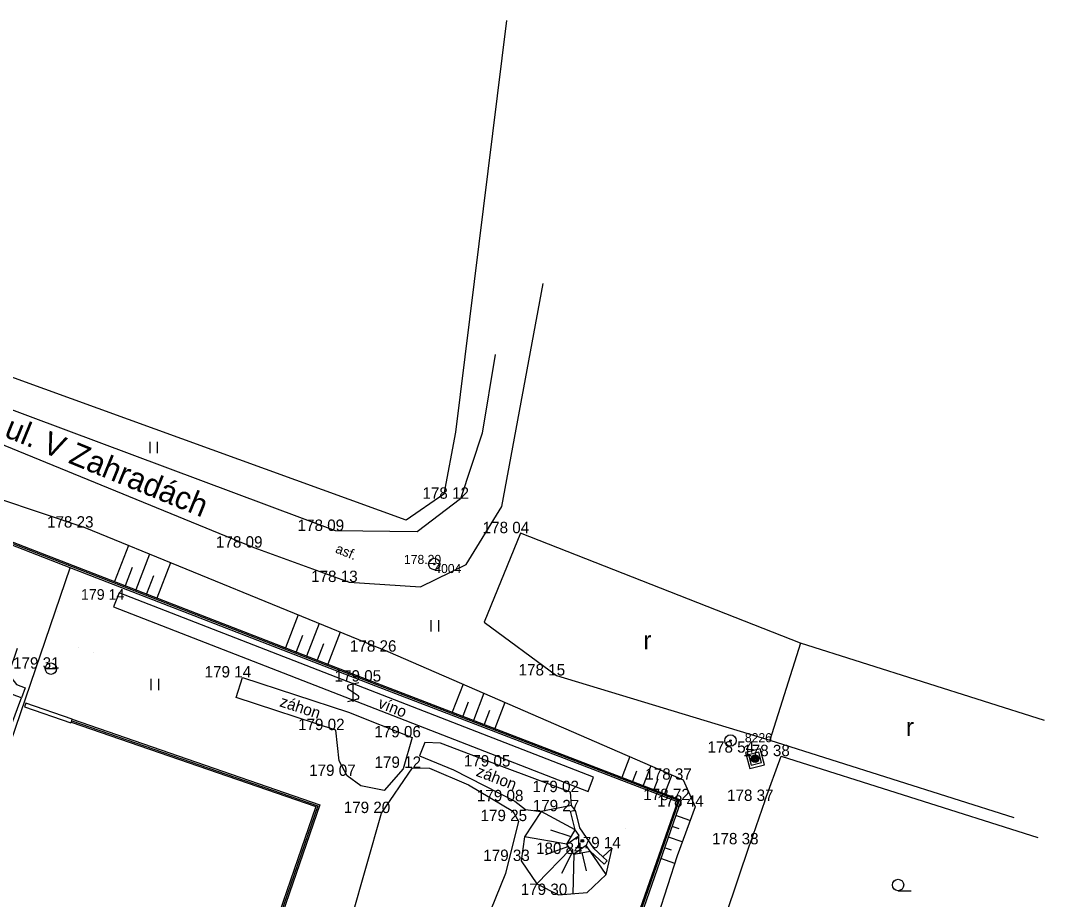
# Model space of a CAD drawing. Extents: x -537755 to -537431, y -1180722 to -1180510.
# Drawn here: x -537505 to -537437.5, y -1180574 to -1180516.1 of the extents above; entities that cross this region are included whole.
import ezdxf

# ---------------------------------------------------------------- set-up
doc = ezdxf.new("R2010")
doc.units = 0
for name, color, linetype in [('Vrstva 1', 7, 'Continuous'), ('Vrstva 10', 7, 'Continuous'), ('Vrstva 11', 7, 'Continuous'), ('Vrstva 14', 7, 'Continuous'), ('Vrstva 15', 7, 'Continuous'), ('Vrstva 21', 7, 'Continuous'), ('Vrstva 22', 7, 'Continuous'), ('Vrstva 23', 7, 'Continuous'), ('Vrstva 25', 7, 'Continuous'), ('Vrstva 3', 7, 'Continuous'), ('Vrstva 35', 7, 'Continuous'), ('Vrstva 36', 7, 'Continuous'), ('Vrstva 39', 7, 'Continuous'), ('Vrstva 40', 7, 'Continuous'), ('Vrstva 41', 7, 'Continuous'), ('Vrstva 49', 7, 'Continuous'), ('Vrstva 5', 7, 'Continuous'), ('Vrstva 7', 7, 'Continuous'), ('Vrstva 8', 7, 'Continuous')]:
    doc.layers.add(name, color=color, linetype=linetype)

msp = doc.modelspace()

# ---------------------------------------------------------------- linework, layer by layer
at = {"layer": 'Vrstva 1'}
for p, q in [((-537474.54, -1180543.31), (-537474.54, -1180543.31)), ((-537475.97, -1180547.63), (-537475.97, -1180547.63)), ((-537473.23, -1180548.13), (-537473.23, -1180548.13)), ((-537500.72, -1180549.53), (-537500.72, -1180549.53)), ((-537484.2, -1180549.75), (-537484.2, -1180549.75)), ((-537478.81, -1180549.8), (-537478.81, -1180549.8)), ((-537472, -1180549.9), (-537472, -1180549.9)), ((-537489.58, -1180550.85), (-537489.58, -1180550.85)), ((-537475.59, -1180551.97), (-537475.59, -1180551.97)), ((-537500.94, -1180552.35), (-537500.94, -1180552.35)), ((-537483.31, -1180553.12), (-537483.31, -1180553.12)), ((-537478.6, -1180553.43), (-537478.6, -1180553.43)), ((-537498.65, -1180554.29), (-537498.65, -1180554.29)), ((-537502.53, -1180555.07), (-537502.53, -1180555.07)), ((-537474.39, -1180555.77), (-537474.39, -1180555.77)), ((-537501.16, -1180557.42), (-537501.16, -1180557.42)), ((-537500.15, -1180557.78), (-537500.15, -1180557.78)), ((-537480.75, -1180557.71), (-537480.75, -1180557.71)), ((-537502.96, -1180558.83), (-537502.96, -1180558.83)), ((-537490.33, -1180559.41), (-537490.33, -1180559.41)), ((-537469.63, -1180559.28), (-537469.63, -1180559.28)), ((-537504.66, -1180560.09), (-537504.66, -1180560.09)), ((-537481.76, -1180559.68), (-537481.76, -1180559.68)), ((-537501.67, -1180562.13), (-537501.67, -1180562.13)), ((-537501.59, -1180562.27), (-537501.59, -1180562.27)), ((-537483.34, -1180561.7), (-537483.34, -1180561.7)), ((-537484.17, -1180562.88), (-537484.17, -1180562.88)), ((-537479.14, -1180563.36), (-537479.14, -1180563.36)), ((-537455.57, -1180563.55), (-537455.57, -1180563.55)), ((-537478.32, -1180563.69), (-537478.32, -1180563.69)), ((-537477.27, -1180563.74), (-537477.27, -1180563.74)), ((-537456.21, -1180564.11), (-537456.21, -1180564.11)), ((-537483.97, -1180564.91), (-537483.97, -1180564.91)), ((-537478.66, -1180564.57), (-537478.66, -1180564.57)), ((-537457.173, -1180564.368), (-537457.173, -1180564.368)), ((-537456.3, -1180564.34), (-537456.3, -1180564.34)), ((-537454.82, -1180564.6), (-537454.82, -1180564.6)), ((-537479.74, -1180565.44), (-537479.74, -1180565.44)), ((-537479.13, -1180565.37), (-537479.13, -1180565.37)), ((-537478, -1180565.4), (-537478, -1180565.4)), ((-537476.42, -1180565.51), (-537476.42, -1180565.51)), ((-537473.24, -1180565.28), (-537473.24, -1180565.28)), ((-537456.79, -1180565.19), (-537456.79, -1180565.19)), ((-537483.44, -1180565.9), (-537483.44, -1180565.9)), ((-537461.28, -1180566.15), (-537461.28, -1180566.15)), ((-537482.54, -1180566.55), (-537482.54, -1180566.55)), ((-537480.99, -1180566.87), (-537480.99, -1180566.87)), ((-537475.44, -1180566.5), (-537475.44, -1180566.5)), ((-537468.72, -1180566.97), (-537468.72, -1180566.97)), ((-537467.37, -1180566.46), (-537467.37, -1180566.46)), ((-537472.38, -1180567.57), (-537472.38, -1180567.57)), ((-537461.55, -1180567.55), (-537461.55, -1180567.55)), ((-537461.41, -1180567.5), (-537461.41, -1180567.5)), ((-537455.89, -1180567.55), (-537455.89, -1180567.55)), ((-537485.37, -1180567.87), (-537485.37, -1180567.87)), ((-537481.16, -1180568.35), (-537481.16, -1180568.35)), ((-537472.52, -1180568.22), (-537472.52, -1180568.22)), ((-537471.67, -1180568.12), (-537471.67, -1180568.12)), ((-537470.65, -1180568.25), (-537470.65, -1180568.25)), ((-537468.7, -1180568.23), (-537468.7, -1180568.23)), ((-537468.64, -1180567.85), (-537468.64, -1180567.85)), ((-537460.5, -1180567.93), (-537460.5, -1180567.93)), ((-537472.14, -1180568.88), (-537472.14, -1180568.88)), ((-537486, -1180569.4), (-537486, -1180569.4)), ((-537468.4, -1180569.46), (-537468.4, -1180569.46)), ((-537465.07, -1180569.38), (-537465.07, -1180569.38)), ((-537471.74, -1180569.92), (-537471.74, -1180569.92)), ((-537486.39, -1180570.69), (-537486.39, -1180570.69)), ((-537468.48, -1180571.05), (-537468.48, -1180571.05)), ((-537467.42, -1180570.86), (-537467.42, -1180570.86)), ((-537465.96, -1180570.67), (-537465.96, -1180570.67)), ((-537456.88, -1180570.41), (-537456.88, -1180570.41)), ((-537471.96, -1180571.51), (-537471.96, -1180571.51)), ((-537466.79, -1180571.44), (-537466.79, -1180571.44)), ((-537461.68, -1180571.17), (-537461.68, -1180571.17)), ((-537473, -1180572.34), (-537473, -1180572.34)), ((-537469.49, -1180573.75), (-537469.49, -1180573.75)), ((-537467.61, -1180573.58), (-537467.61, -1180573.58))]:
    msp.add_line(p, q, dxfattribs=at)
at = {"layer": 'Vrstva 10'}
for p, q in [((-537473.23, -1180548.13), (-537470.52, -1180533.43)), ((-537473.68, -1180538.12), (-537474.54, -1180543.31)), ((-537484.2, -1180549.75), (-537506.9, -1180541.26)), ((-537506.96, -1180543.74), (-537489.58, -1180550.85)), ((-537475.59, -1180551.97), (-537473.23, -1180548.13)), ((-537478.81, -1180549.8), (-537484.2, -1180549.75)), ((-537489.58, -1180550.85), (-537483.31, -1180553.12))]:
    msp.add_line(p, q, dxfattribs=at)
for points in [[(-537474.54, -1180543.31), (-537475.97, -1180547.63), (-537478.81, -1180549.8)], [(-537483.31, -1180553.12), (-537478.6, -1180553.43), (-537475.59, -1180551.97)], [(-537456.97, -1180564.52), (-537456.79, -1180565.19), (-537456.12, -1180565.01), (-537456.3, -1180564.34), (-537456.97, -1180564.52)]]:
    msp.add_lwpolyline(points, dxfattribs=at)
at = {"layer": 'Vrstva 11'}
for points in [[(-537505.19, -1180557.5), (-537505.76, -1180559.19), (-537505.24, -1180559.87), (-537504.66, -1180560.09), (-537504.902, -1180560.752)], [(-537505.93, -1180563.54), (-537505.011, -1180561.039), (-537504.902, -1180560.752), (-537505.211, -1180560.635), (-537506.757, -1180560.051)], [(-537457.173, -1180564.368), (-537456.891, -1180565.423), (-537455.927, -1180565.164), (-537456.21, -1180564.11), (-537457.173, -1180564.368)]]:
    msp.add_lwpolyline(points, dxfattribs=at)
at = {"layer": 'Vrstva 14'}
for p, q in [((-537514.76, -1180544.83), (-537500.72, -1180549.53)), ((-537500.72, -1180549.53), (-537480.75, -1180557.71)), ((-537480.75, -1180557.71), (-537461.28, -1180566.15)), ((-537468.941, -1180570.391), (-537468.4, -1180569.46)), ((-537468.48, -1180571.05), (-537467.42, -1180570.86))]:
    msp.add_line(p, q, dxfattribs=at)
for points in [[(-537461.28, -1180566.15), (-537460.5, -1180567.93), (-537461.68, -1180571.17), (-537462.95, -1180575.12)], [(-537468.409, -1180568.159), (-537468.64, -1180567.85), (-537470.65, -1180568.25), (-537471.74, -1180569.92), (-537471.96, -1180571.51), (-537470.938, -1180573.026), (-537469.49, -1180573.75)], [(-537469.49, -1180573.75), (-537467.61, -1180573.58), (-537466.353, -1180572.39), (-537465.96, -1180570.67), (-537466.569, -1180571.235)]]:
    msp.add_lwpolyline(points, dxfattribs=at)
at = {"layer": 'Vrstva 15'}
for p, q in [((-537497.846, -1180550.707), (-537498.771, -1180553.095)), ((-537496.458, -1180551.276), (-537497.372, -1180553.637)), ((-537495.069, -1180551.845), (-537495.973, -1180554.178)), ((-537497.609, -1180552.172), (-537498.071, -1180553.366)), ((-537496.21, -1180552.713), (-537496.672, -1180553.908)), ((-537486.662, -1180555.288), (-537487.502, -1180557.457)), ((-537485.274, -1180555.857), (-537486.103, -1180557.999)), ((-537486.383, -1180556.644), (-537486.803, -1180557.728)), ((-537483.886, -1180556.426), (-537484.704, -1180558.54)), ((-537484.984, -1180557.185), (-537485.404, -1180558.27)), ((-537475.796, -1180559.857), (-537476.504, -1180561.7)), ((-537474.419, -1180560.454), (-537475.104, -1180562.238)), ((-537475.45, -1180561.047), (-537475.804, -1180561.969)), ((-537474.05, -1180561.586), (-537474.404, -1180562.507)), ((-537473.041, -1180561.052), (-537473.704, -1180562.776)), ((-537464.788, -1180564.629), (-537465.315, -1180565.999)), ((-537464.352, -1180565.583), (-537464.615, -1180566.268)), ((-537463.411, -1180565.226), (-537463.915, -1180566.537)), ((-537462.951, -1180566.121), (-537463.215, -1180566.806)), ((-537462.033, -1180565.823), (-537462.515, -1180567.076)), ((-537468.4, -1180569.46), (-537470.65, -1180568.25)), ((-537460.833, -1180568.844), (-537461.765, -1180568.518)), ((-537468.671, -1180569.925), (-537470.004, -1180569.487)), ((-537461.556, -1180569.386), (-537462.012, -1180569.227)), ((-537468.941, -1180570.391), (-537471.74, -1180569.92)), ((-537461.346, -1180570.253), (-537462.259, -1180569.935)), ((-537468.711, -1180570.72), (-537470.938, -1180573.026)), ((-537468.832, -1180570.547), (-537470.362, -1180571.109)), ((-537468.575, -1180570.915), (-537469.306, -1180572.334)), ((-537468.48, -1180571.05), (-537468.55, -1180573.665)), ((-537467.648, -1180572.165), (-537467.95, -1180570.955)), ((-537466.353, -1180572.39), (-537467.42, -1180570.86)), ((-537462.05, -1180570.802), (-537462.507, -1180570.643)), ((-537461.841, -1180571.67), (-537462.754, -1180571.351))]:
    msp.add_line(p, q, dxfattribs=at)
at = {"layer": 'Vrstva 21'}
for p, q in [((-537498.469, -1180553.824), (-537498.831, -1180554.756)), ((-537467.189, -1180565.994), (-537498.469, -1180553.824)), ((-537498.831, -1180554.756), (-537467.551, -1180566.926)), ((-537467.551, -1180566.926), (-537467.189, -1180565.994))]:
    msp.add_line(p, q, dxfattribs=at)
for centre, radius in [((-537477.69, -1180551.93), 0.375), ((-537477.69, -1180551.93), 0.05), ((-537458.163, -1180563.571), 0.375), ((-537458.163, -1180563.571), 0.05)]:
    msp.add_circle(centre, radius, dxfattribs=at)
at = {"layer": 'Vrstva 23'}
for p, q in [((-537472, -1180549.9), (-537474.39, -1180555.77)), ((-537453.546, -1180557.157), (-537472, -1180549.9)), ((-537474.39, -1180555.77), (-537469.63, -1180559.28)), ((-537453.546, -1180557.157), (-537455.57, -1180563.55)), ((-537437.46, -1180562.25), (-537453.546, -1180557.157)), ((-537490.76, -1180560.721), (-537490.33, -1180559.41)), ((-537490.33, -1180559.41), (-537483.34, -1180561.7)), ((-537469.63, -1180559.28), (-537455.57, -1180563.55)), ((-537484.17, -1180562.88), (-537490.76, -1180560.721)), ((-537455.57, -1180563.55), (-537439.484, -1180568.643)), ((-537483.15, -1180575.31), (-537481.16, -1180568.35)), ((-537471.67, -1180568.12), (-537470.65, -1180568.25)), ((-537473, -1180572.34), (-537475.54, -1180578.6))]:
    msp.add_line(p, q, dxfattribs=at)
for points in [[(-537483.34, -1180561.7), (-537479.14, -1180563.36), (-537479.74, -1180565.44), (-537480.99, -1180566.87)], [(-537480.99, -1180566.87), (-537482.54, -1180566.55), (-537483.44, -1180565.9), (-537483.97, -1180564.91), (-537484.17, -1180562.88)], [(-537473.24, -1180565.28), (-537477.27, -1180563.74), (-537478.32, -1180563.69), (-537478.66, -1180564.57), (-537476.42, -1180565.51)], [(-537481.16, -1180568.35), (-537479.13, -1180565.37), (-537478, -1180565.4), (-537475.44, -1180566.5)], [(-537476.42, -1180565.51), (-537472.38, -1180567.57), (-537471.67, -1180568.12)], [(-537468.64, -1180567.85), (-537468.72, -1180566.97), (-537473.24, -1180565.28)], [(-537475.44, -1180566.5), (-537472.52, -1180568.22), (-537472.14, -1180568.88), (-537473, -1180572.34)]]:
    msp.add_lwpolyline(points, dxfattribs=at)
at = {"layer": 'Vrstva 25'}
for radius in [0.25, 0.2, 0.15, 0.1, 0.05]:
    msp.add_circle((-537456.544, -1180564.764), radius, dxfattribs=at)
at = {"layer": 'Vrstva 35'}
msp.add_line((-537503.335, -1180558.83), (-537502.585, -1180558.83), dxfattribs=at)
msp.add_circle((-537502.96, -1180558.83), 0.375, dxfattribs=at)
at = {"layer": 'Vrstva 36'}
for p, q in [((-537496.43, -1180544.626), (-537496.43, -1180543.876)), ((-537495.93, -1180544.626), (-537495.93, -1180543.876)), ((-537477.888, -1180556.38), (-537477.888, -1180555.63)), ((-537477.388, -1180556.38), (-537477.388, -1180555.63)), ((-537496.357, -1180560.252), (-537496.357, -1180559.502)), ((-537495.857, -1180560.252), (-537495.857, -1180559.502)), ((-537483.365, -1180560.171), (-537482.711, -1180560.607)), ((-537482.665, -1180559.764), (-537483.326, -1180559.923)), ((-537483.04, -1180561.014), (-537483.04, -1180559.764)), ((-537482.75, -1180560.852), (-537483.415, -1180561.014)), ((-537447.116, -1180573.467), (-537446.241, -1180573.467))]:
    msp.add_line(p, q, dxfattribs=at)
msp.add_circle((-537447.116, -1180573.092), 0.375, dxfattribs=at)
for centre, start, end in [((-537483.265, -1180560.06), 113.96482, 228.0101), ((-537482.814, -1180560.716), 295.55354, 46.6612)]:
    msp.add_arc(centre, 0.15, start, end, dxfattribs=at)
at = {"layer": 'Vrstva 39'}
for radius in [0.09, 0.0398]:
    msp.add_circle((-537467.929, -1180570.189), radius, dxfattribs=at)
at = {"layer": 'Vrstva 5'}
for p, q in [((-537468.7, -1180568.23), (-537468.409, -1180568.159)), ((-537468.4, -1180569.46), (-537468.7, -1180568.23)), ((-537468.409, -1180568.159), (-537468.122, -1180569.334)), ((-537468.141, -1180569.83), (-537468.4, -1180569.46)), ((-537468.122, -1180569.334), (-537467.193, -1180570.661)), ((-537468.941, -1180570.391), (-537468.141, -1180569.83)), ((-537468.48, -1180571.05), (-537468.941, -1180570.391)), ((-537467.679, -1180570.49), (-537468.48, -1180571.05)), ((-537467.42, -1180570.86), (-537467.679, -1180570.49)), ((-537466.489, -1180571.718), (-537467.42, -1180570.86)), ((-537467.193, -1180570.661), (-537466.569, -1180571.235)), ((-537466.569, -1180571.235), (-537466.285, -1180571.497)), ((-537466.285, -1180571.497), (-537466.489, -1180571.718))]:
    msp.add_line(p, q, dxfattribs=at)
at = {"layer": 'Vrstva 7'}
for p, q in [((-537515.555, -1180546.598), (-537481.76, -1180559.68)), ((-537481.796, -1180559.773), (-537515.381, -1180546.773)), ((-537501.7, -1180552.176), (-537515.2, -1180546.95)), ((-537505.614, -1180563.66), (-537501.7, -1180552.176)), ((-537481.832, -1180559.867), (-537501.7, -1180552.176)), ((-537461.663, -1180567.617), (-537481.832, -1180559.867)), ((-537461.55, -1180567.55), (-537481.796, -1180559.773)), ((-537481.76, -1180559.68), (-537461.41, -1180567.5)), ((-537504.7, -1180561.35), (-537501.65, -1180562.41)), ((-537501.59, -1180562.27), (-537485.37, -1180567.87)), ((-537501.565, -1180562.166), (-537485.241, -1180567.802)), ((-537501.631, -1180562.355), (-537485.495, -1180567.926)), ((-537455.89, -1180567.55), (-537454.82, -1180564.6)), ((-537454.82, -1180564.6), (-537437.89, -1180569.96)), ((-537477.608, -1180613.623), (-537461.55, -1180567.55)), ((-537461.41, -1180567.5), (-537475.176, -1180606.957)), ((-537461.663, -1180567.617), (-537473.031, -1180600.103)), ((-537485.37, -1180567.87), (-537494, -1180592.9)), ((-537485.241, -1180567.802), (-537493.873, -1180592.838)), ((-537486.442, -1180570.674), (-537494.127, -1180592.962)), ((-537458.47, -1180575.1), (-537456.88, -1180570.41))]:
    msp.add_line(p, q, dxfattribs=at)
for points in [[(-537472.921, -1180516.1), (-537476.295, -1180543.235)], [(-537479.535, -1180549.052), (-537507.134, -1180539.034)], [(-537476.295, -1180543.235), (-537477.068, -1180547.319)], [(-537477.068, -1180547.319), (-537479.535, -1180549.052)], [(-537501.65, -1180562.41), (-537501.631, -1180562.355), (-537501.59, -1180562.27), (-537501.565, -1180562.166), (-537504.615, -1180561.106), (-537504.7, -1180561.35)], [(-537485.495, -1180567.926), (-537486, -1180569.4), (-537486.442, -1180570.674)]]:
    msp.add_lwpolyline(points, dxfattribs=at)
at = {"layer": 'Vrstva 8'}
msp.add_line((-537455.89, -1180567.55), (-537456.88, -1180570.41), dxfattribs=at)

# ---------------------------------------------------------------- texts
at = {"layer": 'Vrstva 22'}
msp.add_text('178.20 ', height=0.6, dxfattribs=at).set_placement((-537479.69, -1180551.93))
at = {"layer": 'Vrstva 23'}
for s, p in [('4004', (-537477.69, -1180552.53)), ('8226', (-537457.215, -1180563.682))]:
    msp.add_text(s, height=0.6, dxfattribs=at).set_placement(p)
at = {"layer": 'Vrstva 3'}
for s, height, p in [('178 12 ', 0.75, (-537478.47, -1180547.63)), ('178 23 ', 0.75, (-537503.22, -1180549.53)), ('178 09 ', 0.75, (-537486.7, -1180549.75)), ('178 04 ', 0.75, (-537474.5, -1180549.9)), ('178 09 ', 0.75, (-537492.08, -1180550.85)), ('178 13 ', 0.75, (-537485.81, -1180553.12)), ('179 14 ', 0.7, (-537500.983, -1180554.29)), ('178 26 ', 0.75, (-537483.25, -1180557.71)), ('179 31 ', 0.75, (-537505.46, -1180558.83)), ('179 14 ', 0.75, (-537492.83, -1180559.41)), ('178 15 ', 0.75, (-537472.13, -1180559.28)), ('179 05 ', 0.75, (-537484.26, -1180559.68)), ('179 02 ', 0.75, (-537486.67, -1180562.88)), ('179 06 ', 0.75, (-537481.64, -1180563.36)), ('178 54 ', 0.75, (-537459.673, -1180564.368)), ('178 38 ', 0.75, (-537457.32, -1180564.6)), ('179 12 ', 0.75, (-537481.63, -1180565.37)), ('179 05 ', 0.75, (-537475.74, -1180565.28)), ('179 07 ', 0.75, (-537485.94, -1180565.9)), ('178 37 ', 0.75, (-537463.78, -1180566.15)), ('179 02 ', 0.75, (-537471.22, -1180566.97)), ('179 08 ', 0.75, (-537474.88, -1180567.57)), ('178 72 ', 0.75, (-537463.91, -1180567.5)), ('178 37 ', 0.75, (-537458.39, -1180567.55)), ('179 20 ', 0.75, (-537483.66, -1180568.35)), ('179 27 ', 0.75, (-537471.2, -1180568.23)), ('178 44 ', 0.75, (-537463, -1180567.93)), ('179 25 ', 0.75, (-537474.64, -1180568.88)), ('178 38 ', 0.75, (-537459.38, -1180570.41)), ('180 84 ', 0.75, (-537470.98, -1180571.05)), ('179 14 ', 0.75, (-537468.46, -1180570.67)), ('179 33 ', 0.75, (-537474.46, -1180571.51)), ('179 30 ', 0.75, (-537471.99, -1180573.75))]:
    msp.add_text(s, height=height, dxfattribs=at).set_placement(p)
at = {"layer": 'Vrstva 36'}
for p in [(-537463.906, -1180557.557), (-537446.6, -1180563.279)]:
    msp.add_text('r', height=1.2, dxfattribs=at).set_placement(p)
at = {"layer": 'Vrstva 40'}
msp.add_text('asf.', height=0.65, rotation=337.75098, dxfattribs=at).set_placement((-537484.26, -1180551.16))
at = {"layer": 'Vrstva 41'}
for s, rotation, p in [('záhon', 341.86064, (-537487.938, -1180561.3)), ('víno', 338.74066, (-537481.459, -1180561.385)), ('záhon', 339.08644, (-537474.988, -1180565.881))]:
    msp.add_text(s, height=0.75, rotation=rotation, dxfattribs=at).set_placement(p)
at = {"layer": 'Vrstva 49'}
msp.add_text('ul. V Zahradách', height=1.5, rotation=337.75098, dxfattribs=at).set_placement((-537506.106, -1180543.511))

doc.saveas('drawing.dxf')
